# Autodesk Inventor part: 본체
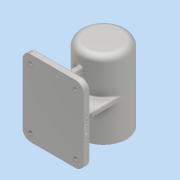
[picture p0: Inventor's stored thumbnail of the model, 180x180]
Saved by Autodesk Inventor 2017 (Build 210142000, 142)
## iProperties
Part Number: 본체
Material: 알루미늄 6061
Document SubType Name: Modeling
Designer: mrc
Density: 2.7 g/cm^3
Appearance: 알루미늄 - 평지
Mass: 1026.24 g
Surface Area: 757.016 cm^2
Volume: 380.088 cm^3
Author: mrc
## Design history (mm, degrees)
sketch "스케치1"
  geometry: L1 (0, 56)-(0, -56); L2 (0, 56)-(34, 56); L3 (34, 56)-(34, -56); L4 (34, -56)-(0, -56); L5 (0, 50)-(10.5, 50); L6 (10.5, 50)-(10.5, 47); L7 (10.5, 47)-(16, 47); L8 (16, 47)-(16, 43); L9 (16, 43)-(17.5, 43); L10 (17.5, 43)-(17.5, 25); L11 (17.5, 25)-(21, 25); L12 (21, 25)-(21, 13); L13 (21, 13)-(24, 13); L14 (24, 13)-(24, -41); L15 (24, -41)-(21, -41); L16 (21, -41)-(21, -56); 2 further points
  constraints: 32 end point, 13 perpendicular, 2 horizontal, 2 point on line, 1 coincident, 1 midpoint, 1 vertical
  dimensions: "d0" = 112 distance of L1.start L1.end; "d1" = 21 diameter of L6 L1; "d2" = 32 diameter of L8 L1; "d3" = 35 diameter of L10 L1; "d4" = 68 diameter of L3 L1; "d5" = 48 diameter of L14 L1; "d6" = 42 diameter of L12 L1; "d7" = 42 diameter of L16 L1; "d8" = 15 distance between parallel lines of L4 L15; "d9" = 54 distance between parallel lines of L13 L15; "d10" = 12 distance between parallel lines of L11 L13; "d11" = 18 distance between parallel lines of L9 L11; "d12" = 4 distance between parallel lines of L7 L9; "d13" = 3 distance between parallel lines of L5 L7
revolve "회전1" sketch "스케치1" stored, may be unused: angle "d14" = 90 deg
fillet "모깎기1" dims "d15" = 3
fillet "모깎기2" dims "d16" = 0.3
fillet "모깎기3" dims "d17" = 3
chamfer "모따기1" distance "d18" = 1; stored, may be unused: second distance "d19" = 2, angle "d20" = 45 deg
sketch "스케치2"
  geometry: 2 further points
  constraints: 1 vertical alignment
  dimensions: "d21" = 26 distance of point (0, 0) point (0, 26)
hole "구멍1" sketch "스케치2" at (0, 26) diameter "d22" = 3.242; stored, may be unused: countersink angle "d26" = 90 deg, drill point angle "d28" = 118 deg; dims "d23" = 8, "d24" = 4, "d25" = 2, "d27" = 11
fillet "모깎기4" dims "d32" = 10
sketch "스케치3"
  geometry: L1 (-64, 56)-(-74, 56); L2 (-74, 56)-(-74, -56); L3 (-74, -56)-(-64, -56); L4 (-64, -56)-(-64, 56); 2 further points
  constraints: 8 end point, 2 parallel, 1 horizontal, 1 horizontal alignment, 1 midpoint, 1 perpendicular
  dimensions: "d33" = 10 distance of L3.end L2.end; "d34" = 112 distance of L2.end L1.end; "d37" = 74 distance from line of L2 point (0, 0)
extrude "돌출1" join sketch "스케치3" stored distance "d35" = 90; taper "d36" = 0 deg
fillet "모깎기5" dims "d38" = 12
sketch "스케치4"
  geometry: L1 (29, 18)-(37, 18); L2 (37, 18)-(37, 94); L3 (37, 94)-(29, 94); L4 (29, 94)-(29, 18); L5 (29, 18)-(37, 94); L6 (37, 18)-(29, 94); L7 (0, 0)-(66, 0) reference; L8 (-1, 52)-(67, 52); L9 (67, 52)-(67, 60); L10 (67, 60)-(-1, 60); L11 (-1, 60)-(-1, 52); L12 (-1, 52)-(67, 60); L13 (67, 52)-(-1, 60); 1 further point
  constraints: 24 end point, 4 midpoint, 4 parallel, 2 horizontal, 2 perpendicular
  dimensions: "d39" = 8 distance of L3.end L2.end; "d40" = 18 distance between parallel lines of L1 L7; "d41" = 8 distance of L9.end L8.end; "d42" = 68 distance of L9.end L10.end
extrude "돌출2" join sketch "스케치4" stored distance "d43" = 90; taper "d44" = 0 deg
hole "구멍2" diameter "d47" = 5.5; stored, may be unused: countersink angle "d51" = 90 deg, drill point angle "d53" = 0 deg; dims "d45" = 10, "d46" = 10, "d48" = 8, "d49" = 9.5, "d50" = 5.4, "d52" = 11
fillet "모깎기6" dims "d60" = 3
fillet "모깎기7" dims "d61" = 3
fillet "모깎기8" dims "d62" = 3
fillet "모깎기9" dims "d63" = 3
sketch "스케치7"
  geometry: L1 (-44, -74)-(44, -74) reference; 2 further points
  constraints: 1 vertical alignment, 1 other
  dimensions: "d64" = 3 distance from line of L1 point (0, -71)
feature "엠보싱1" sketch "스케치7" dims "d0" = 112, "d1" = 21, "d2" = 32, "d3" = 35, "d4" = 68, "d5" = 48, "d6" = 42, "d7" = 42, "d8" = 15, "d9" = 54, "d10" = 12, "d11" = 18, "d12" = 4, "d13" = 3, "d65" = 0.5, "d66" = 0
node "솔리드1"
pattern_circular "원형 패턴1" dims angle "d30" = 360 deg
pattern_linear "직사각형 패턴1" dims "d56" = 88, "d59" = 66
